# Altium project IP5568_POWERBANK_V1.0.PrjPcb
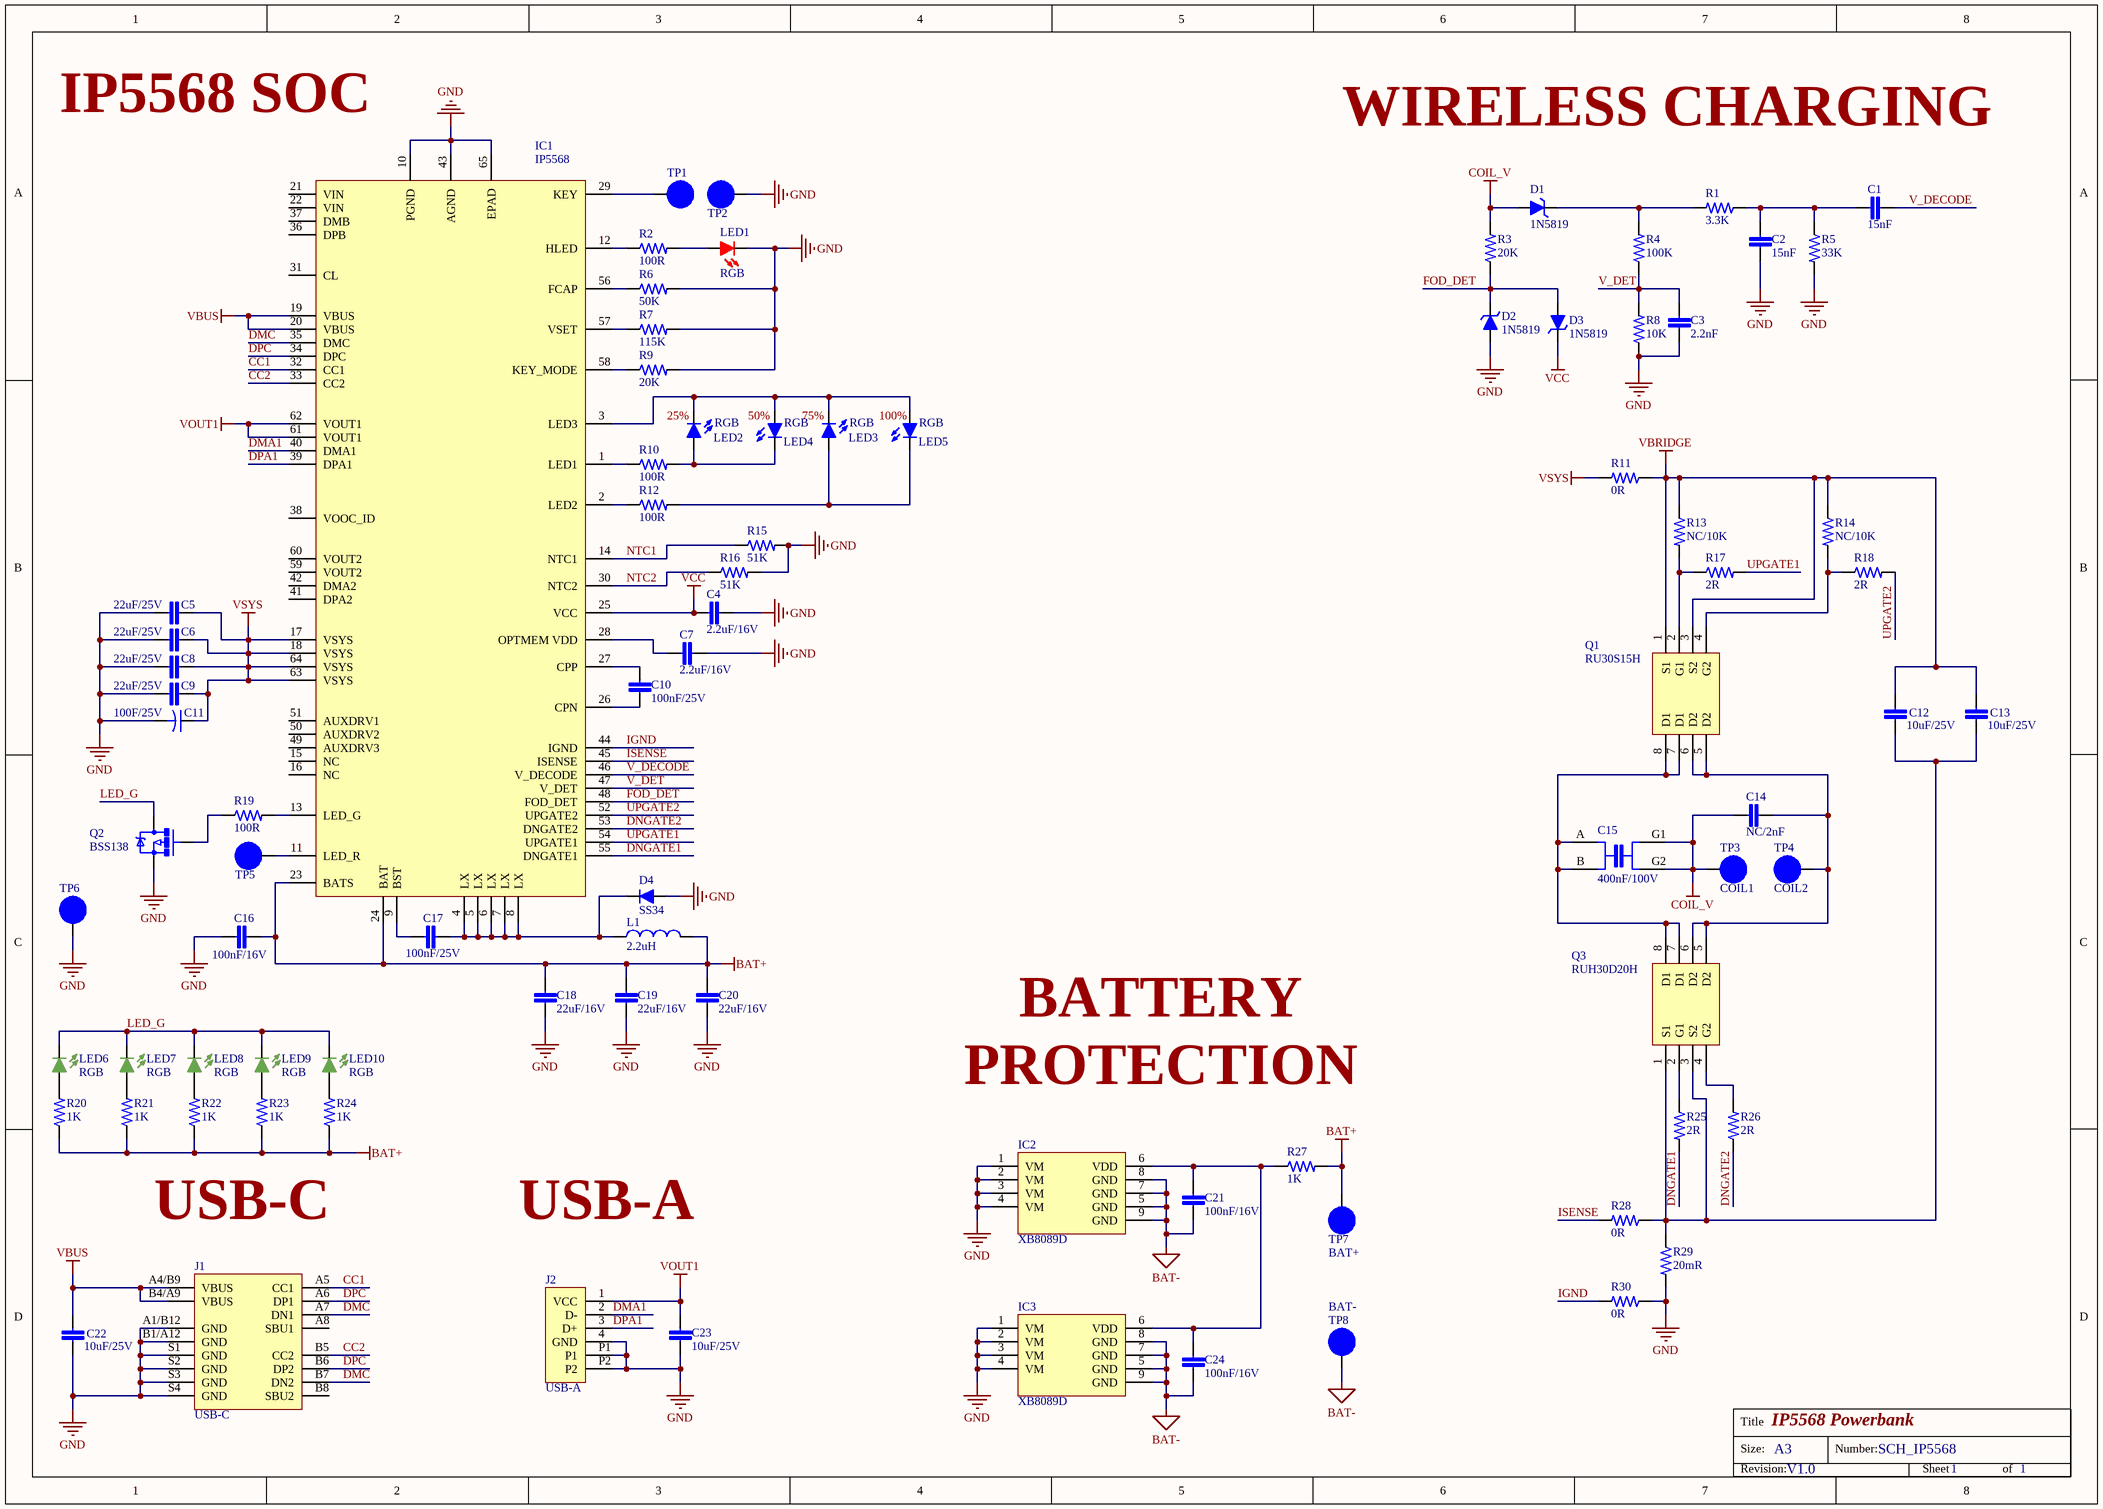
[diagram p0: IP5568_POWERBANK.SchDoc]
1 sheet, 85 parts. Net scope: global (net labels, ports and power ports of the same name join across sheets).
Board file: IP5568_POWERBANK.PcbDoc

## Sheet IP5568_POWERBANK.SchDoc: IP5568 Powerbank
size A3; Organization: Altium Limited; Address1: L3, 12a Rodborough Rd; Address2: Frenchs Forest; Address3: NSW; Address4: Australia 2086; DocumentNumber: SCH_IP5568; Revision: V1.0; SheetNumber: 1; SheetTotal: 1

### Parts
C1  15nF  [C0603]
C2  15nF  [C0603]
C3  2.2nF  [C0603]
C4  2.2uF/16V  [C0603]
C5  22uF/25V  [C0805]
C6  22uF/25V  [C0805]
C7  2.2uF/16V  [C0603]
C8  22uF/25V  [C0805]
C9  22uF/25V  [C0805]
C10  100nF/25V  [C0603]
C11  100F/25V  [CAP_TAND_7343]
C12  10uF/25V  [C0805]
C13  10uF/25V  [C0805]
C14  NC/2nF  [C0603]
C15  400nF/100V  [C1410]
C16  100nF/16V  [C0603]
C17  100nF/25V  [C0603]
C18  22uF/16V  [C0805]
C19  22uF/16V  [C0805]
C20  22uF/16V  [C0805]
C21  100nF/16V  [C0603]
C22  10uF/25V  [C0805]
C23  10uF/25V  [C0805]
C24  100nF/16V  [C0603]
D1  1N5819  [SOD-123]
D2  1N5819  [SOD-123]
D3  1N5819  [SOD-123]
D4  SS34  [DIODE_ DO-214AB(SMC)]
IC1  IP5568  [QFN64]
IC2  XB8089D  [SOP-08]
IC3  XB8089D  [SOP-08]
J1  USB-C  [USB-C_USB4110-GF-A]
J2  USB-A  [USB_A_F]
L1  2.2uH  [INDUCTOR_10X10X4]
LED1  RGB  [LED_RGB]
LED2  RGB  [LED_RGB]
LED3  RGB  [LED_RGB]
LED4  RGB  [LED_RGB]
LED5  RGB  [LED_RGB]
LED6  RGB  [LED_RGB]
LED7  RGB  [LED_RGB]
LED8  RGB  [LED_RGB]
LED9  RGB  [LED_RGB]
LED10  RGB  [LED_RGB]
Q1  RU30S15H  [SO-08]
Q2  BSS138  [SOT23-3]
Q3  RUH30D20H  [SO-08]
R1  3.3K  [R0603]
R2  100R  [R0603]
R3  20K  [R0603]
R4  100K  [R0603]
R5  33K  [R0603]
R6  50K  [R0603]
R7  115K  [R0603]
R8  10K  [R0603]
R9  20K  [R0603]
R10  100R  [R0603]
R11  0R  [R0805]
R12  100R  [R0603]
R13  NC/10K  [R0603]
R14  NC/10K  [R0603]
R15  51K  [R0603]
R16  51K  [R0603]
R17  2R  [R0603]
R18  2R  [R0603]
R19  100R  [R0603]
R20  1K  [R0603]
R21  1K  [R0603]
R22  1K  [R0603]
R23  1K  [R0603]
R24  1K  [R0603]
R25  2R  [R0603]
R26  2R  [R0603]
R27  1K  [R0603]
R28  0R  [R0603]
R29  20mR  [R1206]
R30  0R  [R0603]
TP1  TP  [TESTPOINT_1MM_ROUND]  (value not drawn)  (no BOM)
TP2  TP  [TESTPOINT_1MM_ROUND]  (value not drawn)  (no BOM)
TP3  COIL1  [TEST_POINT_3MM_ROUND]  (no BOM)
TP4  COIL2  [TEST_POINT_3MM_ROUND]  (no BOM)
TP5  TP  [TESTPOINT_1MM_ROUND]  (value not drawn)  (no BOM)
TP6  TP  [TESTPOINT_1MM_ROUND]  (value not drawn)  (no BOM)
TP7  BAT+  [TEST_POINT_3MM_ROUND]  (no BOM)
TP8  BAT-  [TEST_POINT_3MM_ROUND]  (no BOM)

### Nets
BAT+: C16.1 C18.1 C19.1 C20.1 IC1.23(BATS) IC1.24(BAT) L1.2 R20.1 R21.1 R22.1 R23.1 R24.1 R27.2 TP7.1
BAT-: C21.2 C24.2 IC2.5(GND) IC2.7(GND) IC2.8(GND) IC2.9(GND) IC3.5(GND) IC3.7(GND) IC3.8(GND) IC3.9(GND) TP8.1
COIL_V: C14.1 C15.G1 C15.G2 D1.A R3.2 TP3.1
GND: C2.2 C3.2 C4.1 C5.2 C6.2 C7.1 C8.2 C9.2 C11.2 C16.2 C18.2 C19.2 C20.2 C22.2 C23.2 D2.A D4.A IC1.10(PGND) IC1.43(AGND) IC1.65(EPAD) IC2.1(VM) IC2.2(VM) IC2.3(VM) IC2.4(VM) IC3.1(VM) IC3.2(VM) IC3.3(VM) IC3.4(VM) J1.A1/B12(GND) J1.B1/A12(GND) J1.S1(GND) J1.S2(GND) J1.S3(GND) J1.S4(GND) J2.4(GND) J2.P1 J2.P2 LED1.4 Q2.2(S) R5.2 R6.2 R7.2 R8.1 R9.2 R15.2 R16.2 R29.2 R30.1 TP2.1 TP6.1
VBRIDGE: C12.1 C13.1 Q1.1(S1) Q1.3(S2) R11.1 R13.1 R14.1
VBUS: C22.1 IC1.19(VBUS) IC1.20(VBUS) J1.A4/B9(VBUS) J1.B4/A9(VBUS)
VCC: C4.2 D3.K IC1.25(VCC)
VOUT1: C23.1 IC1.61(VOUT1) IC1.62(VOUT1) J2.1(VCC)
VSYS: C5.1 C6.1 C8.1 C9.1 C11.1 IC1.17(VSYS) IC1.18(VSYS) IC1.63(VSYS) IC1.64(VSYS) R11.2
CC1: IC1.32(CC1) J1.A5(CC1)
CC2: IC1.33(CC2) J1.B5(CC2)
DMA1: IC1.40(DMA1) J2.2(D-)
DMC: IC1.35(DMC) J1.A7(DN1) J1.B7(DN2)
DNGATE1: IC1.55(DNGATE1) R25.2
DNGATE2: IC1.53(DNGATE2) R26.1
DPA1: IC1.39(DPA1) J2.3(D+)
DPC: IC1.34(DPC) J1.A6(DP1) J1.B6(DP2)
FOD_DET: D2.K D3.A IC1.48(FOD_DET) R3.1
IGND: IC1.44(IGND) R30.2
ISENSE: IC1.45(ISENSE) R28.2
LED_G: LED6.3 LED7.3 LED8.3 LED9.3 LED10.3 Q2.3(D)
NTC1: IC1.14(NTC1) R15.1
NTC2: IC1.30(NTC2) R16.1
UPGATE1: IC1.54(UPGATE1) R17.2
UPGATE2: IC1.52(UPGATE2) R18.2
V_DECODE: C1.2 IC1.46(V_DECODE)
V_DET: C3.1 IC1.47(V_DET) R4.1 R8.2
NetC1_1: C1.1 C2.1 R1.1 R5.1
NetC7_2: C7.2 IC1.28(OPTMEM_VDD)
NetC10_1: C10.1 IC1.26(CPN)
NetC10_2: C10.2 IC1.27(CPP)
NetC12_2: C12.2 C13.2 Q3.1(S1) Q3.3(S2) R28.1 R29.1
NetC14_2: C14.2 Q1.5(D2) Q1.6(D2) Q3.5(D2) Q3.6(D2) TP4.1
NetC15_A: C15.A C15.B Q1.7(D1) Q1.8(D1) Q3.7(D1) Q3.8(D1)
NetC17_1: C17.1 IC1.9(BST)
NetC17_2: C17.2 D4.K IC1.4(LX) IC1.5(LX) IC1.6(LX) IC1.7(LX) IC1.8(LX) L1.1
NetC21_1: C21.1 C24.1 IC2.6(VDD) IC3.6(VDD) R27.1
NetD1_K: D1.K R1.2 R4.2
NetIC1_1: IC1.1(LED1) R10.1
NetIC1_2: IC1.2(LED2) R12.1
NetIC1_3: IC1.3(LED3) LED2.2 LED3.2 LED4.1 LED5.1
NetIC1_11: IC1.11(LED_R) TP5.1
NetIC1_12: IC1.12(HLED) R2.1
NetIC1_13: IC1.13(LED_G) R19.2
NetIC1_29: IC1.29(KEY) TP1.1
NetIC1_56: IC1.56(FCAP) R6.1
NetIC1_57: IC1.57(VSET) R7.1
NetIC1_58: IC1.58(KEY_MODE) R9.1
NetLED1_1: LED1.1 R2.2
NetLED2_1: LED2.1 LED4.2 R10.2
NetLED3_1: LED3.1 LED5.2 R12.2
NetLED6_1: LED6.1 R20.2
NetLED7_1: LED7.1 R21.2
NetLED8_1: LED8.1 R22.2
NetLED9_1: LED9.1 R23.2
NetLED10_1: LED10.1 R24.2
NetQ1_2: Q1.2(G1) R13.2 R17.1
NetQ1_4: Q1.4(G2) R14.2 R18.1
NetQ2_1: Q2.1(G) R19.1
NetQ3_2: Q3.2(G1) R25.1
NetQ3_4: Q3.4(G2) R26.2

Not connected (* = marked no-connect by the designer): IC1 15(NC) 16(NC) 21(VIN) 22(VIN) 31(CL) 36(DPB) 37(DMB) 38(VOOC_ID) 41(DPA2) 42(DMA2) 49(AUXDRV3) 50(AUXDRV2) 51(AUXDRV1) 59(VOUT2) 60(VOUT2); J1 A8(SBU1) B8(SBU2)

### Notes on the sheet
- IP5568 SOC
- WIRELESS CHARGING
- (near LED2) 25%
- (near LED4) 50%
- (near LED3) 75%
- (near LED5) 100%
- BATTERY
- PROTECTION
- USB-C
- USB-A

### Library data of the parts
C1 C2 = CAPACITOR: Capacitor, 0603, 15nF, 10%, 50V
C3 = CAPACITOR: Capacitor, 0603, 2.2nF, 10%, 50V
C4 C7 = CAPACITOR: Capacitor, 0603, 2.2uF, 10%, 16V
C5 C6 C8 C9 = CAPACITOR: Capacitor, 0805, 22uF, 10%, 25V
C10 C17 = CAPACITOR: Capacitor, 0603, 100nF, 10%, 25V
C11 = CAP_TAN_100uF_25V: KEMET Tantalum Capacitor  100µF/25V Case-D (7343 Metric) 300mOhm; Manufacturer Part Number: T491X107K025AT; Capacitance: 100uF; Tolerance: 10%; ESR (Equivalent Series Resistance): 300mR; Voltage Rating: 25V; Life (Hours): 2000Hour; Leakage Current: 25uA; Polarity: Polar; Dissipation Factor: 8%; Ripple Current: 742mA
C12 C13 C22 C23 = CAPACITOR: Capacitor, 0805, 10uF, 10%, 25V
C14 = CAPACITOR: Capacitor, 0603, NC/2nF, 10%, 50V
C15 = C1410_400nF_100V: 400nF ±20% 100V Ceramic Capacitor X7R 1410 (3524 Metric); Manufacturer: Johanson; Manufacturer Part Number: 101X44W404MV4E
C16 C21 C24 = CAPACITOR: Capacitor, 0603, 100nF, 10%, 16V
C18-C20 = CAPACITOR: Capacitor, 0805, 22uF, 10%, 16V
D1-D3 = DIODE_1N5819: Diode Schottky 40V 1A Surface Mount SOD-123; Manufacturer: Diodes; Manufacturer Part Number: 1N5819HW-7-F; Forward Voltage: 450mV; Peak Reverse Current: 50uA; Element Configuration: Single; Max Forward Surge Current (Ifsm): 25A; Max Power Dissipation: 450mW; Polarity: Standard; Capacitance: 110pF
D4 = DIODE_SS34: Diode Schottky 40V 3A Surface Mount SMC (DO-214AB)
IC1 = IP5568_SOC: Bi-directional PD3.0 and Fast Charge protocol Power Bank & Wireless Charger SOC
IC2 IC3 = XB8089D: XB8089D One Cell Lithium-ion/Polymer Battery Protection IC
J1 = USB-C: USB-C (USB TYPE-C) USB 2.0 Receptacle Connector 24 (16+8 Dummy) Position Surface Mount, Right Angle; Through Hole; Manufacturer: Global Connector Technology; Manufacturer Part Number: USB4110-GF-A
J2 = USB_A_F: USB-A (USB TYPE-A) USB 2.0 Receptacle Connector 4 Position Through Hole, Right Angle; Manufacturer: Amphenol FCI; Manufacturer Part Number: 87520-0010BLF; Plating: Tin; Gender: Female; Connector Type: USB,Receptacle; Number of Ports: 1; Number of Contacts: 4; USB Standard: USB 2.0
L1 = INDUCTOR_2.2UH: 2.2uH ±20% SMD,10x10x4mm Inductors (SMD) RoHS
LED1 = LEDR_RGB: Red, Green, Blue (RGB) 624nm Red, 525nm Green, 470nm Blue LED Indicator - Discrete 2V Red, 3.3V Green, 3.3V Blue 4-SMD; Manufacturer: Everlight; Manufacturer Part Number: EASV3015RGBA0; Color: Blue,Green,Red; Lens Color: Colorless; Test Current: 20mA; Viewing Angle: 100°; Lens Transparency: Clear; Luminous Intensity: 50mcd
LED2-LED5 = LEDB_RGB: Red, Green, Blue (RGB) 624nm Red, 525nm Green, 470nm Blue LED Indicator - Discrete 2V Red, 3.3V Green, 3.3V Blue 4-SMD; Manufacturer: Everlight; Manufacturer Part Number: EASV3015RGBA0; Color: Blue,Green,Red; Lens Color: Colorless; Test Current: 20mA; Viewing Angle: 100°; Lens Transparency: Clear; Luminous Intensity: 50mcd
LED6-LED10 = LEDG_RGB: Red, Green, Blue (RGB) 624nm Red, 525nm Green, 470nm Blue LED Indicator - Discrete 2V Red, 3.3V Green, 3.3V Blue 4-SMD; Manufacturer: Everlight; Manufacturer Part Number: EASV3015RGBA0; Color: Blue,Green,Red; Lens Color: Colorless; Test Current: 20mA; Viewing Angle: 100°; Lens Transparency: Clear; Luminous Intensity: 50mcd
Q1 = RU30S15H: P-Channel Advanced Power MOSFET -30V/-15A
Q2 = BSS138-7-F: N-Channel 50V 200mA (Ta) 300mW (Ta) Surface Mount SOT-23-3; Manufacturer: Diodes; Nominal Vgs: 1.2V; Gate to Source Voltage (Vgs): 20V; Rds On Max: 3.5R; Input Capacitance: 50pF; Number of Elements: 1; Turn-Off Delay Time: 20ns; Element Configuration: Single; Fall Time: 25ns; Rise Time: 10ns
Q3 = RUH30D20H: N-Channel Advanced Power MOSFET 30V/20A
R1 = RESISTOR: Resistor, 0603R, 3.3K, 1%
R2 R10 R12 R19 = RESISTOR: Resistor, 0603R, 100R, 1%
R3 R9 R27 = RESISTOR: Resistor, 0603R, 20K, 1%
R4 = RESISTOR: Resistor, 0603R, 100K, 1%
R5 = RESISTOR: Resistor, 0603R, 33K, 1%
R6 = RESISTOR: Resistor, 0603R, 50K, 1%
R7 = RESISTOR: Resistor, 0603R, 115K, 1%
R8 = RESISTOR: Resistor, 0603R, 10K, 1%
R11 = RESISTOR: Resistor, 0805R, 0R, 1%
R13 R14 = RESISTOR: Resistor, 0603R, NC/10K, 1%
R15 R16 = RESISTOR: Resistor, 0603R, 51K, 1%
R17 R18 R25 R26 = RESISTOR: Resistor, 0603R, 2R, 1%
R20-R24 = RESISTOR: Resistor, 0603R, 1K, 1%
R28 R30 = RESISTOR: Resistor, 0603R, 0R, 1%
R29 = RESISTOR: Resistor, 1206R, 20mR, 1%
TP1-TP8 = TEST_POINT: SMD Test Point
